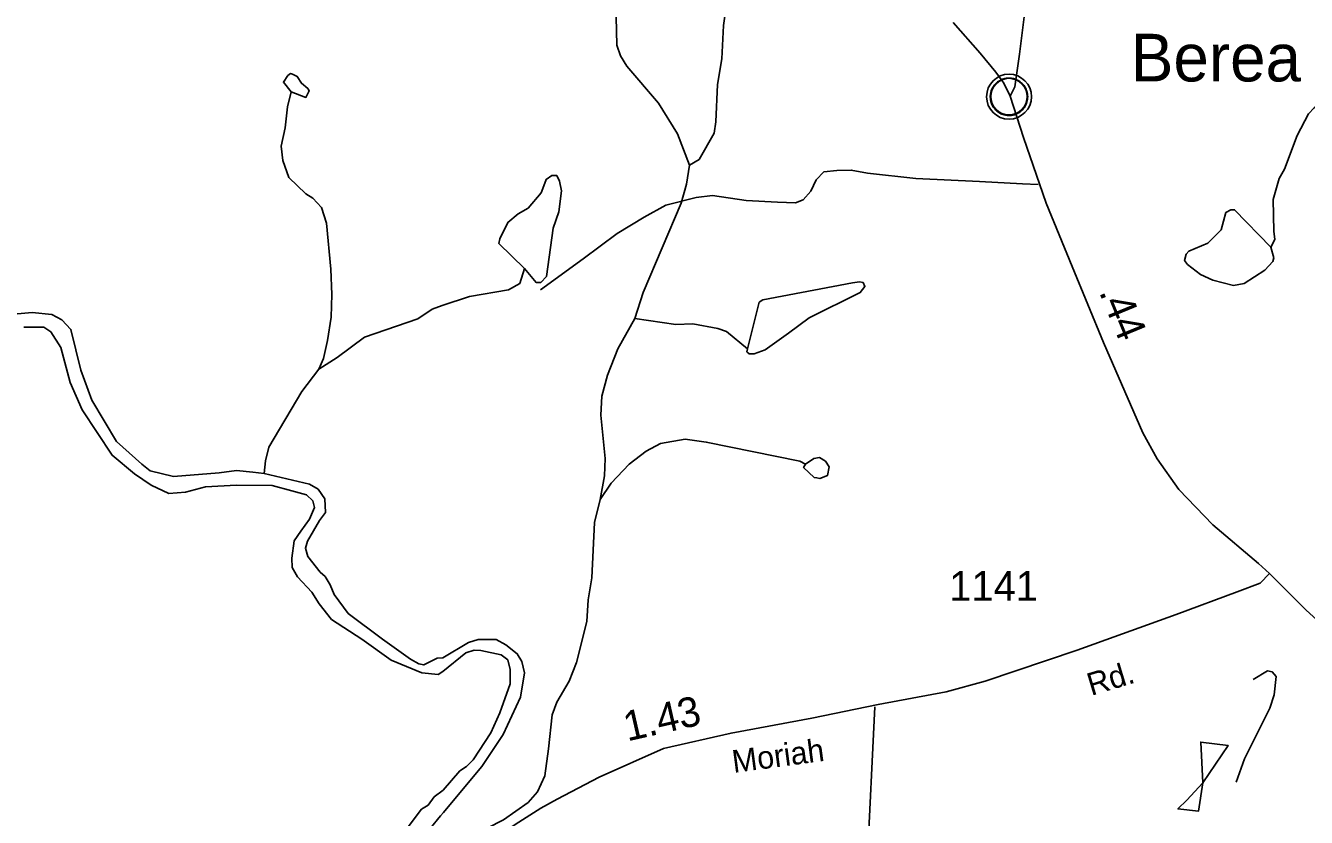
# Model space of a CAD drawing. Extents: x 2056842 to 2160602, y 826753 to 1016856.
# Drawn here: x 2071991 to 2077365, y 932569 to 935892 of the extents above; entities that cross this region are included whole.
import ezdxf

# ---------------------------------------------------------------- set-up
doc = ezdxf.new("R2010")
doc.units = 0
for name, color, linetype in [('Exist Civil Demographics Community CELL', 7, 'Continuous'), ('Exist Civil Demographics Community Label', 7, 'Continuous'), ('Exist Hydrographic Creek Single Shore', 7, 'Continuous'), ('Exist Hydrographic Misc Water Feature', 7, 'Continuous'), ('Exist Hydrographic Pond Under 1500 Sq Ft', 7, 'Continuous'), ('Exist Hydrographic River Shore', 7, 'Continuous'), ('Exist Road Non-System Type 51', 7, 'Continuous'), ('Exist Road Primary US Attributed', 7, 'Continuous'), ('Exist Road Primary US Mileage Hundredths English Label', 7, 'Continuous'), ('Exist Road Secondary Mileage Hundredths English Label', 7, 'Continuous'), ('Exist Road Secondary Type 51 Attributed', 7, 'Continuous'), ('Exist Road Secondary Type 51 Label', 7, 'Continuous'), ('Exist Road Secondary Type 51 Number Label', 7, 'Continuous')]:
    doc.layers.add(name, color=color, linetype=linetype)

msp = doc.modelspace()

# ---------------------------------------------------------------- linework, layer by layer
at = {"layer": 'Exist Civil Demographics Community CELL'}
msp.add_lwpolyline([(2076039.8, 935605.9), (2076040.8, 935611.4), (2076042.6, 935618), (2076045.5, 935625.2), (2076048.5, 935631), (2076051.8, 935636.7), (2076055.6, 935641.8), (2076059.5, 935646.2), (2076064.1, 935650.8), (2076069.6, 935655.4), (2076075.1, 935659), (2076079.9, 935661.9), (2076085, 935664.4), (2076090.5, 935666.7), (2076096.1, 935668.5), (2076100.4, 935669.6), (2076105.3, 935670.4), (2076109.4, 935671.1), (2076115.8, 935671.3), (2076120.2, 935671.2), (2076125.9, 935671), (2076130.8, 935670.3), (2076135.7, 935669.3), (2076140.7, 935667.9), (2076145.8, 935665.9), (2076152.5, 935663), (2076158.8, 935659.5), (2076163.8, 935656), (2076169, 935651.9), (2076172.3, 935648.8), (2076176.4, 935644.4), (2076180.3, 935639.7), (2076183.4, 935635.1), (2076186.5, 935630.1), (2076188.9, 935625), (2076191, 935620), (2076192.5, 935614.9), (2076193.8, 935610.4), (2076194.9, 935604.3), (2076195.5, 935599.6), (2076195.8, 935593.6), (2076195.6, 935587.8), (2076195.1, 935582.1), (2076194.1, 935576.6), (2076192.5, 935570.5), (2076190.6, 935564.6), (2076188.3, 935559.6), (2076185.1, 935553.6), (2076181.9, 935548.3), (2076178.4, 935543.6), (2076174.2, 935538.8), (2076168.9, 935533.9), (2076163.9, 935529.7), (2076158.9, 935526.3), (2076154.5, 935523.8), (2076147.7, 935520.6), (2076140.6, 935517.8), (2076134.6, 935516.4), (2076128, 935515.1), (2076123.6, 935514.6), (2076119.1, 935514.3), (2076113.5, 935514.3), (2076109.2, 935514.8), (2076103.6, 935515.5), (2076097.7, 935516.8), (2076093.1, 935518.1), (2076087.9, 935520), (2076083.3, 935522), (2076079.4, 935524.2), (2076072.6, 935528.3), (2076067, 935532.6), (2076062.1, 935537), (2076057.7, 935541.9), (2076054.5, 935545.9), (2076051.5, 935550), (2076047.4, 935557.1), (2076045.7, 935560.7), (2076044, 935564.7), (2076041.4, 935572.9), (2076039.8, 935579.9), (2076039.2, 935585.1), (2076038.8, 935591.4), (2076038.8, 935596.1), (2076039.3, 935602.6)], close=True, dxfattribs=at)
for centre, radius in [((2076117.5, 935593.4), 94.3), ((2076117.2, 935593.7), 76.7)]:
    msp.add_circle(centre, radius, dxfattribs=at)
at = {"layer": 'Exist Hydrographic Creek Single Shore'}
for points in [[(2075258.1, 937565.5), (2075244.4, 937485.4), (2075222.6, 937437.3), (2075131, 937309.1), (2075009.8, 937066.7), (2074832.6, 936786.1), (2074754.9, 936696), (2074721.1, 936659.8), (2074677.4, 936561.7), (2074661.4, 936509.6), (2074639.9, 936385.5), (2074592.3, 936285.4), (2074498.8, 936125.1), (2074469.3, 935929.1), (2074471.7, 935809), (2074487.9, 935765.1), (2074514, 935721.1), (2074646.4, 935565.6), (2074726.8, 935437.9), (2074777.3, 935306)], [(2075240.1, 936323.4), (2075148.4, 936253.2), (2075104.5, 936209), (2075002.8, 936080.7), (2074963, 936036.5), (2074933.1, 935990.5), (2074919.4, 935892.5), (2074911.8, 935752.4), (2074894.1, 935644.4), (2074886.8, 935488.3), (2074880.8, 935440.3), (2074817.2, 935330.1), (2074777.3, 935306)], [(2074777.3, 935306), (2074763.5, 935225.9), (2074741.8, 935145.9), (2074582.9, 934771.4), (2074547.4, 934663.3)], [(2074084.8, 934871.9), (2074064.9, 934809.8), (2074016.9, 934783.6), (2073853.1, 934755.1), (2073739.3, 934716.8)], [(2073221.3, 934449.8), (2073297.8, 934499.6), (2073412.5, 934583.7), (2073637.2, 934661.8), (2073697.3, 934701.3), (2073739.3, 934716.8)], [(2074547.4, 934663.3), (2074475.6, 934535.1), (2074432.2, 934424.9), (2074408.4, 934336.8), (2074404.7, 934256.9), (2074423.1, 934075), (2074419.4, 934002.9), (2074401.8, 933902.8)], [(2072991.9, 934012.3), (2072997, 934065.9), (2073011, 934123.3), (2073149.9, 934356.7), (2073221.3, 934449.8)], [(2074401.8, 933902.8), (2074378, 933806.8), (2074366.8, 933574.9), (2074351, 933482.8), (2074345.4, 933390.7), (2074302, 933218.6), (2074272, 933140.5), (2074220.3, 933052.4), (2074200.5, 933000.3), (2074185.1, 932856.3), (2074169.3, 932744.2), (2074139.6, 932676.1), (2074099.8, 932632), (2073996, 932559.7), (2073927.9, 932523.5), (2073864.2, 932503.3), (2073828.3, 932479.2), (2073744.4, 932376.9)]]:
    msp.add_lwpolyline(points, dxfattribs=at)
at = {"layer": 'Exist Hydrographic Misc Water Feature'}
for points in [[(2077773.5, 935789.4), (2077556.1, 935626.7), (2077512, 935624.6), (2077398.2, 935546.2), (2077374.5, 935522.1), (2077326.7, 935430), (2077273.2, 935289.9), (2077251.4, 935249.8), (2077225.6, 935161.7), (2077228, 935029.7), (2077232.1, 934993.7), (2077216.2, 934961.7)], [(2073221.3, 934449.8), (2073240.4, 934494.5), (2073258.3, 934569.7), (2073273.6, 934667.9), (2073276.1, 934763.6), (2073272.3, 934869.4), (2073253.7, 935062.7), (2073232, 935129), (2073196.3, 935167.3), (2073167, 935186.4), (2073096, 935254.3), (2073069.8, 935326.2), (2073063.6, 935386.3), (2073079.6, 935462.3), (2073089.5, 935550.2), (2073105.3, 935614.3)], [(2074169.7, 935230.1), (2074175.4, 935246.1), (2074199.4, 935262.2), (2074219.5, 935262.2), (2074231.4, 935238.3), (2074239.6, 935198.4), (2074227.9, 935110.3), (2074204.1, 935042.2)], [(2074084.8, 934871.9), (2073976.3, 934977.5), (2073980.4, 934997.5), (2074014.1, 935065.6), (2074057.9, 935101.8), (2074099.8, 935125.9), (2074153.7, 935190.1), (2074169.7, 935230.1)], [(2077216.2, 934961.7), (2077063.8, 935119.2), (2077047.8, 935119.1), (2077027.7, 935107), (2077008, 935035), (2076952.3, 934978.9)], [(2074204.1, 935042.2), (2074176.7, 934838.2), (2074152.9, 934814.1), (2074132.8, 934814), (2074084.8, 934871.9)], [(2076952.3, 934978.9), (2076872.3, 934944.6), (2076860.4, 934932.5), (2076854.4, 934906.6), (2076866.5, 934888.6), (2076920.7, 934846.7), (2076972.8, 934822.9), (2077058.7, 934801.2)], [(2077058.7, 934801.2), (2077104.8, 934809.4), (2077190.5, 934865.7), (2077224.6, 934901.8), (2077228.3, 934917.7), (2077216.2, 934961.7)], [(2075019.6, 934534.8), (2075069.1, 934730.9), (2075085, 934741), (2075460.9, 934812.1), (2075490.6, 934816.2)], [(2075490.6, 934816.2), (2075504.8, 934814.3), (2075512.8, 934796.4), (2075492.9, 934772.3), (2075279.2, 934665.6)], [(2075019.6, 934534.8), (2074931.5, 934608.5), (2074895.4, 934620.4), (2074791.4, 934640.1), (2074719.4, 934637.9), (2074547.4, 934663.3)], [(2075279.2, 934665.6), (2075191.5, 934601.4), (2075093.7, 934531), (2075047.7, 934514.9), (2075027.6, 934514.8), (2075017.8, 934522.8), (2075019.6, 934534.8)], [(2075263.2, 934051.6), (2075239, 934063.5), (2074847, 934144.3), (2074758.8, 934156), (2074655.1, 934137.7), (2074595.2, 934105.5), (2074523.2, 934051.3), (2074447.5, 933971), (2074401.8, 933902.8)], [(2077141.9, 933147.5), (2077201.8, 933183.7), (2077221.9, 933179.8), (2077237.9, 933159.8), (2077230.1, 933083.8), (2077212.3, 933027.8), (2077105, 932815.5), (2077071.2, 932717.3)]]:
    msp.add_lwpolyline(points, dxfattribs=at)
at = {"layer": 'Exist Hydrographic Pond Under 1500 Sq Ft'}
for points in [[(2073105.1, 935614), (2073073.1, 935654), (2073091.1, 935682.2), (2073103, 935690.1), (2073110.9, 935688)], [(2073110.9, 935688), (2073131, 935678.1), (2073149.1, 935650.1), (2073175.2, 935628.3)], [(2073175.2, 935628.3), (2073181.3, 935618.3), (2073167.2, 935590.4), (2073105.1, 935614)], [(2075262.9, 934051.6), (2075298.9, 934075.5), (2075322.9, 934079.5), (2075346.9, 934063.6)], [(2075311.3, 933993.5), (2075299.2, 933995.7), (2075255.1, 934037.3), (2075262.9, 934051.6)], [(2075346.9, 934063.6), (2075363.1, 934039.7), (2075355.1, 934003.7), (2075323.1, 933991.6), (2075311.3, 933993.5)], [(2076930.5, 932714.3), (2076921.9, 932885.4), (2077036.5, 932871.4), (2076930.5, 932714.3)], [(2076930.5, 932714.3), (2076912.9, 932595.7), (2076825.9, 932605.1), (2076863.7, 932642.1), (2076930.5, 932714.3)]]:
    msp.add_lwpolyline(points, dxfattribs=at)
at = {"layer": 'Exist Hydrographic River Shore'}
for points in [[(2071240.5, 934896.9), (2071300.4, 934849.7), (2071394.7, 934829.3), (2071471.2, 934826.7), (2071541.3, 934811.4), (2071624.7, 934799.4), (2071686.6, 934783.4), (2071857, 934706), (2071892.6, 934693.4), (2071956.7, 934682.7), (2072018.8, 934688.2), (2072100.7, 934679.8), (2072142.8, 934656.4), (2072181, 934616.6), (2072222.7, 934446), (2072268.6, 934319.7), (2072373.1, 934146.3), (2072478.1, 934050.9), (2072514.2, 934023.3), (2072612.2, 933999.3), (2072803.2, 934014.9), (2072875.9, 934025.1), (2072944.7, 934017.4), (2072991.9, 934012.3)], [(2071983.1, 934625.8), (2072032, 934626.1), (2072068.2, 934626.1), (2072096.5, 934606.7), (2072139.3, 934540.6), (2072178.1, 934393.7), (2072227.8, 934278.9), (2072354, 934088.9), (2072448.3, 934011.2), (2072518.4, 933963.3), (2072592.1, 933928.8), (2072661.7, 933933.3), (2072745.9, 933956.2), (2072875.9, 933962.6), (2073026.3, 933962.2), (2073107.6, 933939.6), (2073170.1, 933923.1), (2073195.6, 933897.6), (2073203.2, 933869.5), (2073182.8, 933821), (2073145.8, 933770), (2073117.8, 933729.2), (2073107.6, 933657.1), (2073110.2, 933617.6), (2073131.8, 933578.1), (2073191.7, 933514.3), (2073222.3, 933465.8), (2073274.6, 933399.5), (2073401.6, 933316.9), (2073525.6, 933229.1), (2073653.8, 933176.3), (2073722.1, 933168.7), (2073742, 933180.9)], [(2072991.9, 934012.3), (2073182.8, 933967.7), (2073218.5, 933946), (2073246.5, 933906.5), (2073249.1, 933849.1), (2073224.9, 933814.7), (2073173.9, 933727.9), (2073165, 933699.2), (2073175.2, 933663.5), (2073227, 933598.3), (2073247.8, 933580.6), (2073269.5, 933544.9), (2073286.1, 933504.1), (2073344.7, 933425), (2073489.2, 933316.9), (2073605.6, 933233.1), (2073641.6, 933213.3), (2073661.6, 933209.3), (2073717.6, 933237.4), (2073741.6, 933238.8)], [(2074068.3, 933073.6), (2074083.8, 933175.6), (2074073.7, 933223.7), (2074053.7, 933255.7), (2074005.6, 933293.4), (2073965.3, 933315.2), (2073889.5, 933315.2), (2073849.6, 933302.9), (2073741.6, 933238.8)], [(2073742, 933180.9), (2073837.7, 933259.2), (2073873.8, 933271.3), (2073901.7, 933269.3), (2073985.8, 933251.6), (2074013.9, 933229.7), (2074023.9, 933189.8)], [(2074023.9, 933189.8), (2074024.1, 933129.7), (2073980.4, 933007.6), (2073942.7, 932923.5), (2073869.1, 932811.2), (2073841.2, 932783.2), (2073813.3, 932765.1), (2073743.6, 932682.9)], [(2074068.3, 933073.6), (2073994.5, 932917.6), (2073905.1, 932783.3), (2073777.5, 932630.7), (2073744.9, 932590.4)], [(2073743.6, 932682.9), (2073705.7, 932655.9), (2073680, 932621.2), (2073652.6, 932603.7), (2073562.9, 932485.3), (2073493.2, 932345.2)], [(2073561.3, 932345.1), (2073644.9, 932469.4), (2073731.5, 932576), (2073744.9, 932590.4)]]:
    msp.add_lwpolyline(points, dxfattribs=at)
at = {"layer": 'Exist Road Non-System Type 51'}
for points in [[(2076240.1, 935225.3), (2076173.9, 935227.9), (2075993.3, 935237.5), (2075726.2, 935250.3), (2075523.1, 935272.7), (2075455.2, 935285.5), (2075394.5, 935283.9), (2075340.1, 935277.5), (2075308.1, 935243.9), (2075285.7, 935197.4), (2075253.7, 935160.6), (2075221.8, 935147.8), (2075146.6, 935151), (2075013.9, 935157.4), (2074873.2, 935178.2), (2074804.4, 935170.2), (2074678.1, 935138.2), (2074586.4, 935087.6), (2074472.8, 935018.7), (2074330.5, 934913.1), (2074151.4, 934783.5)], [(2075554.8, 933033.2), (2075522.9, 932373.2), (2075508.8, 932353.1), (2074896.9, 932341.2)]]:
    msp.add_lwpolyline(points, dxfattribs=at)
at = {"layer": 'Exist Road Primary US Attributed'}
for points in [[(2075882.9, 935904.6), (2075995.7, 935775.7), (2076061.6, 935696.9), (2076095.2, 935649.7), (2076122.8, 935595.7)], [(2076122.8, 935595.7), (2076178.3, 935421.7), (2076272.7, 935146.5), (2076382.9, 934880.2), (2076514, 934561.8), (2076678.5, 934183.4), (2076739.1, 934073.5), (2076830.3, 933945.5), (2076972.6, 933796.7), (2077164, 933634.3), (2077210.8, 933592)], [(2077210.8, 933592), (2077222, 933581.9), (2077363.5, 933439.5), (2077518.6, 933298.6), (2077651.3, 933217), (2077782.4, 933159.4), (2077868.8, 933124.2)]]:
    msp.add_lwpolyline(points, dxfattribs=at)
at = {"layer": 'Exist Road Secondary Type 51 Attributed'}
for points in [[(2076122.8, 935595.7), (2076141.2, 935634.1), (2076161.6, 935771.3), (2076182.3, 935939.4)], [(2073449, 932064.6), (2073520.8, 932106.2), (2073629.1, 932173), (2073712.1, 932232.1), (2073822.8, 932351), (2073886.3, 932411.3), (2073966.4, 932484.3), (2074045, 932538.8), (2074152.5, 932608.2), (2074221.2, 932646), (2074397.3, 932738.7), (2074667.5, 932858.2), (2074951.2, 932922.9), (2075290.6, 932985.8), (2075568.9, 933043.3), (2075853.5, 933096.3), (2076016.9, 933141.2), (2076403, 933270.6), (2076818.7, 933420.6), (2077075.4, 933515.9), (2077170.6, 933551.8), (2077210.8, 933592)]]:
    msp.add_lwpolyline(points, dxfattribs=at)

# ---------------------------------------------------------------- texts
at = {"layer": 'Exist Civil Demographics Community Label'}
msp.add_text('Berea', height=200, dxfattribs=at).set_placement((2076628.9, 935657.4))
at = {"layer": 'Exist Road Primary US Mileage Hundredths English Label'}
msp.add_text('.44', height=125, rotation=292.3807, dxfattribs=at).set_placement((2076494, 934774.5))
at = {"layer": 'Exist Road Secondary Mileage Hundredths English Label'}
msp.add_text('1.43', height=125, rotation=12.8443, dxfattribs=at).set_placement((2074515.7, 932887.7))
at = {"layer": 'Exist Road Secondary Type 51 Label'}
for s, rotation, p in [('Rd.', 16.8187, (2076462.2, 933078.8)), ('Moriah', 7.5567, (2074961.7, 932755.8))]:
    msp.add_text(s, height=95, rotation=rotation, dxfattribs=at).set_placement(p)
at = {"layer": 'Exist Road Secondary Type 51 Number Label'}
msp.add_text('1141', height=125, dxfattribs=at).set_placement((2075866.8, 933478))

doc.saveas('drawing.dxf')
